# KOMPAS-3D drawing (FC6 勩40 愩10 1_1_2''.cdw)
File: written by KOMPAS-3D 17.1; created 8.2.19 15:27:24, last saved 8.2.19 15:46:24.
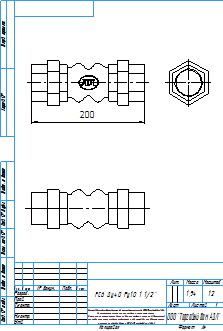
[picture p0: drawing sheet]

Sheet 1: A4, portrait

Title block, sheet 1: name: FC6 Ду40 Ру10 1 1/2''; mass: 1,94; sheets: 1; sheet format: A4; stored path: \\adlc.lan\data\АДЛ_ПКД\3D-модели\ADL production\Гибкие вставки серии FC\FC6\KOMPAS 2D\FC6 Ду40 Ру10 1_1_2''.cdw

Views: Вид 1
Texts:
  kka
  adl
  Рама для чертежей
  Лит-Масса-Масштаб
  Материал-Предприятие
  Масштаб
  Изм.
  Лист
  № докум.
  Подп.
  Дата
  Лит.
  Разраб.
  Пров.
  Т.контр.
  Листов
  Внимание! Данный продукт является объектом авторского права ООО «Торговый Дом АДЛ».
  Запрещается изменение, копирование, распространение
  (в том числе путем копирования на другие сайты и ресурсы в Интернете)
  или любое иное использование информации и объектов без предварительного
  согласия правообладателя (ООО «Торговый Дом АДЛ»).
  Н.контр.
  Утв.
  ООО "Торговый дом АДЛ"
  Изменение
  Номер документа
  Подпись
  Обозначение документа
  Наименование изделия
  Масса изделия по ГОСТ 2.109-73
  Порядковый номер листа
  Общее количество листов в документе
  Характер работы, выполненной лицом, подписавшим документ
  Наименование или индекс предприятия, выпускающего документ
  Инв. № подл.
  Подп. и дата
  Взам. инв. №
  Инв. № дубл.
  Инвентарный номер подлинника по ГОСТ 2.501-68
  Подпись принявшего подлинник в отдел технической документации
  Инвентарный номер подлинника, взамен которого выпущен данный подлинник
  Инвентарный номер дубликата по ГОСТ 2.502-68
  Подпись принявшего дубликат в отдел технической документации
  Справ. №
  Перв. примен.
  Обозначение документа, взамен или на основании которого выпущен данный документ
  Обозначение документа, в котором впервые записан данный документ
  Подпись лица, копировавшего чертеж
  Обозначение формата листа
  !Рама для чертежа
Dimensions and other numbers on the sheet: 200; 1:2; 1; 1,94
